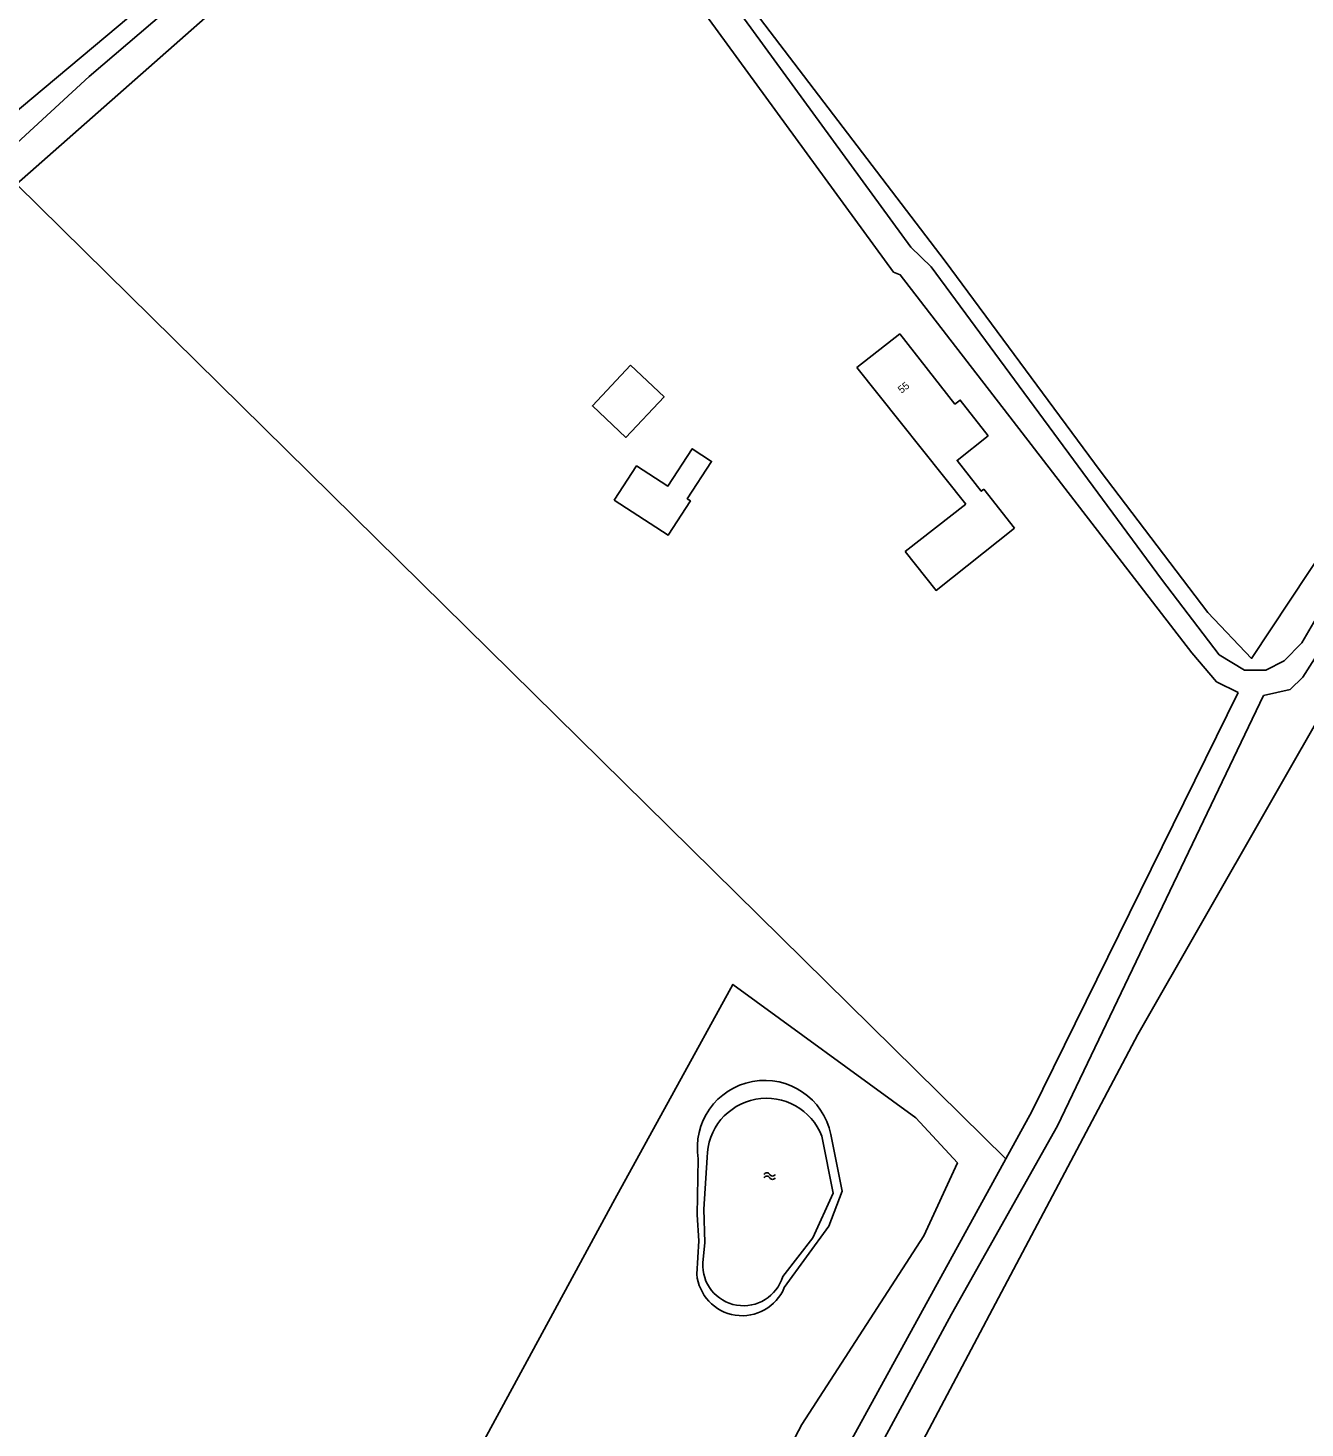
# Model space of a CAD drawing. Extents: x 134297 to 137000, y 403500 to 406000.
# Drawn here: x 136168.4 to 136340, y 403918.2 to 404106.3 of the extents above; entities that cross this region are included whole.
import ezdxf

# ---------------------------------------------------------------- set-up
doc = ezdxf.new("R2010")
doc.units = 0
for name, color, linetype in [('gg-afsc-draadraster', 7, 'Continuous'), ('gg-afsc-lijn draadraster', 7, 'Continuous'), ('gg-anno-huisnummerreeks BGT', 7, 'Continuous'), ('gg-bbg-gedigitaliseerde bebouwing', 7, 'Continuous'), ('gg-bbg-gedigitaliseerde bijgebouw', 7, 'Continuous'), ('gg-bbg-hoofdgebouw', 7, 'Continuous'), ('gg-knt-bronhoudergrens', 7, 'Continuous'), ('gg-knt-onverhard', 7, 'Continuous'), ('gg-kntw-bovenkant insteek waterloop', 7, 'Continuous'), ('gg-kntw-waterlijn', 7, 'Continuous'), ('gt-grn-groengrens', 7, 'Continuous'), ('gt-symb-watersymbool', 7, 'Continuous')]:
    doc.layers.add(name, color=color, linetype=linetype)

# ---------------------------------------------------------------- blocks, each defined once
blk = doc.blocks.new('gt0-WA')
at = {"layer": 'gt-symb-watersymbool'}
for centre, start, end in [((-0.32, 0.02), 28.0725, 151.9275), ((0.43, 0.42), 208.0725, 331.9275), ((-0.32, -0.43), 28.0725, 151.9275), ((0.43, -0.03), 208.0725, 331.9275)]:
    blk.add_arc(centre, 0.425, start, end, dxfattribs=at)

msp = doc.modelspace()

# ---------------------------------------------------------------- linework, layer by layer
at = {"layer": 'gg-afsc-draadraster'}
msp.add_lwpolyline([(136238.01, 404145.41), (136291.68, 404074.98), (136312.51, 404046.8), (136326.97, 404027.77), (136332.85, 404021.61), (136355.98, 404056.53), (136424.58, 404064.5), (136423.36, 404080.36), (136423.83, 404085.94), (136425.22, 404091.86), (136430.27, 404101.61), (136454.12, 404143.13)], dxfattribs=at)
at = {"layer": 'gg-afsc-lijn draadraster'}
msp.add_lwpolyline([(136238.01, 404145.41), (136291.68, 404074.98), (136312.51, 404046.8), (136326.97, 404027.77), (136332.85, 404021.61), (136355.98, 404056.53), (136424.58, 404064.5), (136423.36, 404080.36), (136423.83, 404085.94), (136425.22, 404091.86), (136430.27, 404101.61), (136454.12, 404143.13)], dxfattribs=at)
at = {"layer": 'gg-bbg-gedigitaliseerde bebouwing'}
for p, q in [((136285.56, 404065.22), (136279.82, 404060.72)), ((136279.82, 404060.72), (136294.43, 404042.33)), ((136294.43, 404042.33), (136286.31, 404035.97))]:
    msp.add_line(p, q, dxfattribs=at)
for points in [[(136297.47, 404051.52), (136293.27, 404048.22), (136296.51, 404044.08), (136296.88, 404044.37)], [(136301, 404039.11), (136290.46, 404030.74), (136286.31, 404035.97)]]:
    msp.add_lwpolyline(points, dxfattribs=at)
at = {"layer": 'gg-bbg-gedigitaliseerde bijgebouw'}
for points in [[(136249.41, 404061.01), (136253.91, 404056.78), (136248.78, 404051.32), (136244.28, 404055.54), (136249.41, 404061.01)], [(136247.22, 404042.87), (136250.22, 404047.48), (136254.41, 404044.76), (136257.68, 404049.79), (136260.29, 404048.09), (136257.02, 404043.06), (136257.44, 404042.78), (136254.44, 404038.17), (136247.22, 404042.87)]]:
    msp.add_lwpolyline(points, dxfattribs=at)
at = {"layer": 'gg-bbg-hoofdgebouw'}
msp.add_line((136301, 404039.11), (136296.88, 404044.37), dxfattribs=at)
msp.add_lwpolyline([(136297.47, 404051.52), (136293.7, 404056.33), (136292.97, 404055.78), (136285.56, 404065.22)], dxfattribs=at)
at = {"layer": 'gg-knt-bronhoudergrens'}
msp.add_line((136229.33, 404147.48), (136133.77, 404067.41), dxfattribs=at)
for points in [[(136355.06, 404036.49), (136352.69, 404032.48), (136317.57, 403971.05), (136305.68, 403948.59)], [(136118.48, 403728.43), (136154.73, 403713.23), (136175.05, 403748.35), (136187.43, 403766.89), (136199.26, 403790.68), (136207.07, 403802.2), (136224.13, 403834.87), (136235.9, 403853.13), (136255.48, 403886.47), (136272.42, 403918.61), (136288.82, 403944.01), (136293.32, 403953.8), (136287.71, 403959.84), (136263.15, 403977.79), (136247.28, 403948.91), (136168.8, 403804.17), (136138.01, 403753.78), (136118.48, 403728.43)], [(136305.68, 403948.59), (136288.71, 403916.51), (136262.46, 403868.9)]]:
    msp.add_lwpolyline(points, dxfattribs=at)
at = {"layer": 'gg-knt-onverhard'}
for points in [[(135992.34, 403933.8), (136026.33, 403963.71), (136082.98, 404013.55), (136148.58, 404073.96), (136176.66, 404099.82), (136234.38, 404149.17), (136287.06, 404076.9)], [(136284.71, 404073.5), (136233.64, 404143.65), (136214.96, 404127.77), (136166.9, 404085.37)], [(136346.79, 404036.07), (136339.61, 404023.69), (136337.21, 404021.26), (136334.75, 404020.02), (136331.88, 404020.03), (136328.47, 404022.1), (136320.73, 404032.24), (136289.77, 404074.22), (136287.06, 404076.9)], [(136284.71, 404073.5), (136285.64, 404073.15), (136300.79, 404053.51), (136324.81, 404022.37)], [(136334.45, 404016.63), (136338.01, 404017.43), (136339.73, 404019.1), (136343.8, 404025.47), (136349.79, 404035.66), (136352.54, 404039.1), (136355.99, 404042.32), (136359.65, 404044.8), (136363.48, 404046.74), (136367.81, 404048.41), (136372.53, 404049.55), (136378.73, 404050.63), (136386.23, 404051.58), (136399.33, 404052.52), (136411.3, 404053.37)], [(136324.81, 404022.37), (136328.14, 404018.47), (136331.06, 404017.03)], [(136299.83, 403954.35), (136303.32, 403960.69), (136331.06, 404017.03)], [(136334.45, 404016.63), (136306.78, 403958.77), (136292.52, 403933.45), (136169.98, 403706.56)], [(135993.23, 403920.73), (135997.97, 403916.43), (136048.71, 403739.88), (136094.01, 403597.93), (136096.82, 403595.11), (136101.04, 403596.52), (136156.43, 403697.26), (136236.49, 403842.87), (136276.9, 403912.56), (136299.83, 403954.35)]]:
    msp.add_lwpolyline(points, dxfattribs=at)
at = {"layer": 'gg-kntw-bovenkant insteek waterloop'}
msp.add_line((136277.81, 403949.98), (136276.3, 403957.61), dxfattribs=at)
for points in [[(136258.31, 403938.84), (136258.57, 403943.34), (136258.36, 403946.83), (136258.5, 403954.34)], [(136270.06, 403937.04), (136276.04, 403945.3), (136277.81, 403949.98)]]:
    msp.add_lwpolyline(points, dxfattribs=at)
for centre, radius, start, end in [((136267.43, 403955.83), 9.05, 11.3676, 189.4295), ((136264.4, 403939.37), 6.12, 184.941, 337.637)]:
    msp.add_arc(centre, radius, start, end, dxfattribs=at)
at = {"layer": 'gg-kntw-waterlijn'}
msp.add_line((136276.61, 403949.74), (136275.1, 403957.37), dxfattribs=at)
for points in [[(136259.1, 403940.38), (136259.37, 403943.08), (136259.26, 403947.57), (136259.7, 403954.51)], [(136269.84, 403938.52), (136273.87, 403943.71), (136276.61, 403949.74)]]:
    msp.add_lwpolyline(points, dxfattribs=at)
for centre, radius, start, end in [((136267.67, 403954.51), 7.97, 21.0628, 179.9761), ((136264.58, 403940.08), 5.49, 176.9054, 343.5305)]:
    msp.add_arc(centre, radius, start, end, dxfattribs=at)
at = {"layer": 'gt-grn-groengrens'}
msp.add_line((136166.9, 404085.37), (136299.83, 403954.35), dxfattribs=at)

# ---------------------------------------------------------------- block references
at = {"layer": 'gt-symb-watersymbool', "rotation": 180}
msp.add_blockref('gt0-WA', (136268.15, 403952.02), dxfattribs=at)

# ---------------------------------------------------------------- texts
at = {"layer": 'gg-anno-huisnummerreeks BGT'}
msp.add_text('55', height=1, rotation=38.1, dxfattribs=at).set_placement((136285.8, 404057.17))

doc.saveas('drawing.dxf')
